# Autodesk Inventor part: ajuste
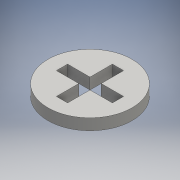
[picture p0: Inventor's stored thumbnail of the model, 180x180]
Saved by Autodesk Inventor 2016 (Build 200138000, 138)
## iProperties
Created: 2016-06
Part Number: ajuste
Material: Genérico
Document SubType Name: Modeling
Designer: adm
Density: 1 g/cm^3
Appearance: Valor por defecto
Author: adm
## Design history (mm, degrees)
sketch "Boceto1"
  geometry: L1 (-2, -10)-(2, -10); L2 (2, -10)-(2, 10); L3 (2, 10)-(-2, 10); L4 (-2, 10)-(-2, -10); L5 (-2, -10)-(2, 10); L6 (2, -10)-(-2, 10); L7 (-10, -2)-(10, -2); L8 (10, -2)-(10, 2); L9 (10, 2)-(-10, 2); L10 (-10, 2)-(-10, -2); L11 (-10, -2)-(10, 2); L12 (10, -2)-(-10, 2); C1 r 15 at (0, 0); 1 further point
  constraints: 24 end point, 4 midpoint, 4 parallel, 2 horizontal, 2 perpendicular, 1 centre point, 1 coincident
  dimensions: "d0" = 30 diameter of C1; "d1" = 4 distance of L3.end L2.end; "d2" = 20 distance of L1.end L2.end; "d3" = 20 distance of L9.end L8.end; "d4" = 4 distance of L8.end L7.end
extrude "Extrusión1" new body sketch "Boceto1" distance "d5" = 4; taper "d6" = 0 deg
node "Sólido1"
